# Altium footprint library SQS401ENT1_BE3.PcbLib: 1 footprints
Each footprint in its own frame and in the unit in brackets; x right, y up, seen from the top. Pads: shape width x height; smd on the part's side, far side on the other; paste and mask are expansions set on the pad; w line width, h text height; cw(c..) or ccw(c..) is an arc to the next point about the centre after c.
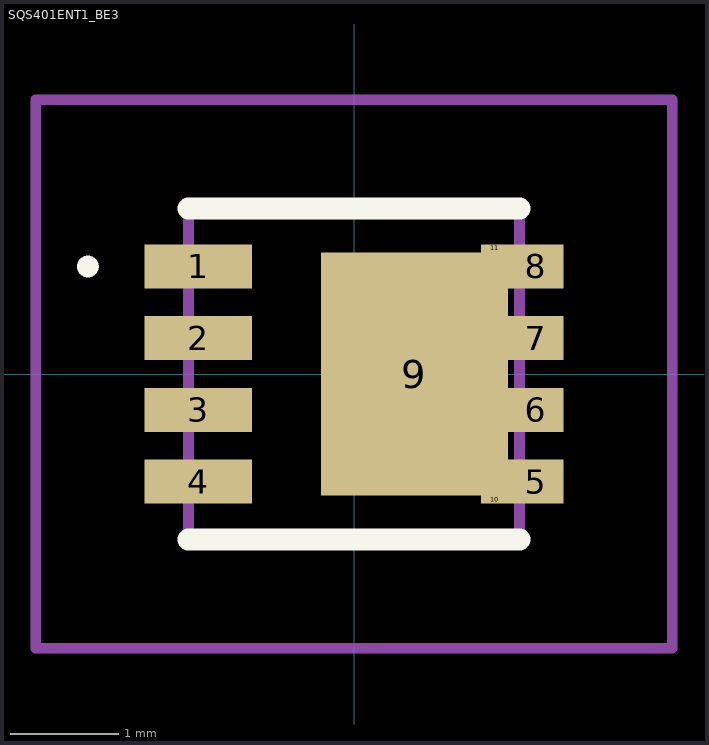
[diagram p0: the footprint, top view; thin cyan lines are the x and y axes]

## SQS401ENT1_BE3 [mm]
pads (11):
  rect 0.99x0.405 smd: 1(-1.435,0.99) 2(-1.435,0.33) 3(-1.435,-0.33) 4(-1.435,-0.99)
  rect 0.51x0.405 smd: 5(1.675,-0.99) 6(1.675,-0.33) 7(1.675,0.33) 8(1.675,0.99)
  rect 1.725x2.235 smd: 9(0.557,0)
  rect 0.25x0.077 smd: 10(1.295,-1.156) 11(1.295,1.156)
Top Overlay:
  lines w0.1: -2.5,0.99 -2.5,0.99 ; -2.5,0.99 ccw(c-2.45,0.99) -2.4,0.99 ; -2.5,0.99 cw(c-2.45,0.99) -2.4,0.99 ; -2.4,0.99 -2.4,0.99
  lines w0.2: -1.525,-1.525 1.525,-1.525 ; -1.525,1.525 1.525,1.525
Mechanical 15:
  lines w0.1: -1.525,-1.525 1.525,-1.525 1.525,1.525 -1.525,1.525 -1.525,-1.525
Mechanical 20:
  lines w0.1: -2.93,-2.525 2.93,-2.525 2.93,2.525 -2.93,2.525 -2.93,-2.525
